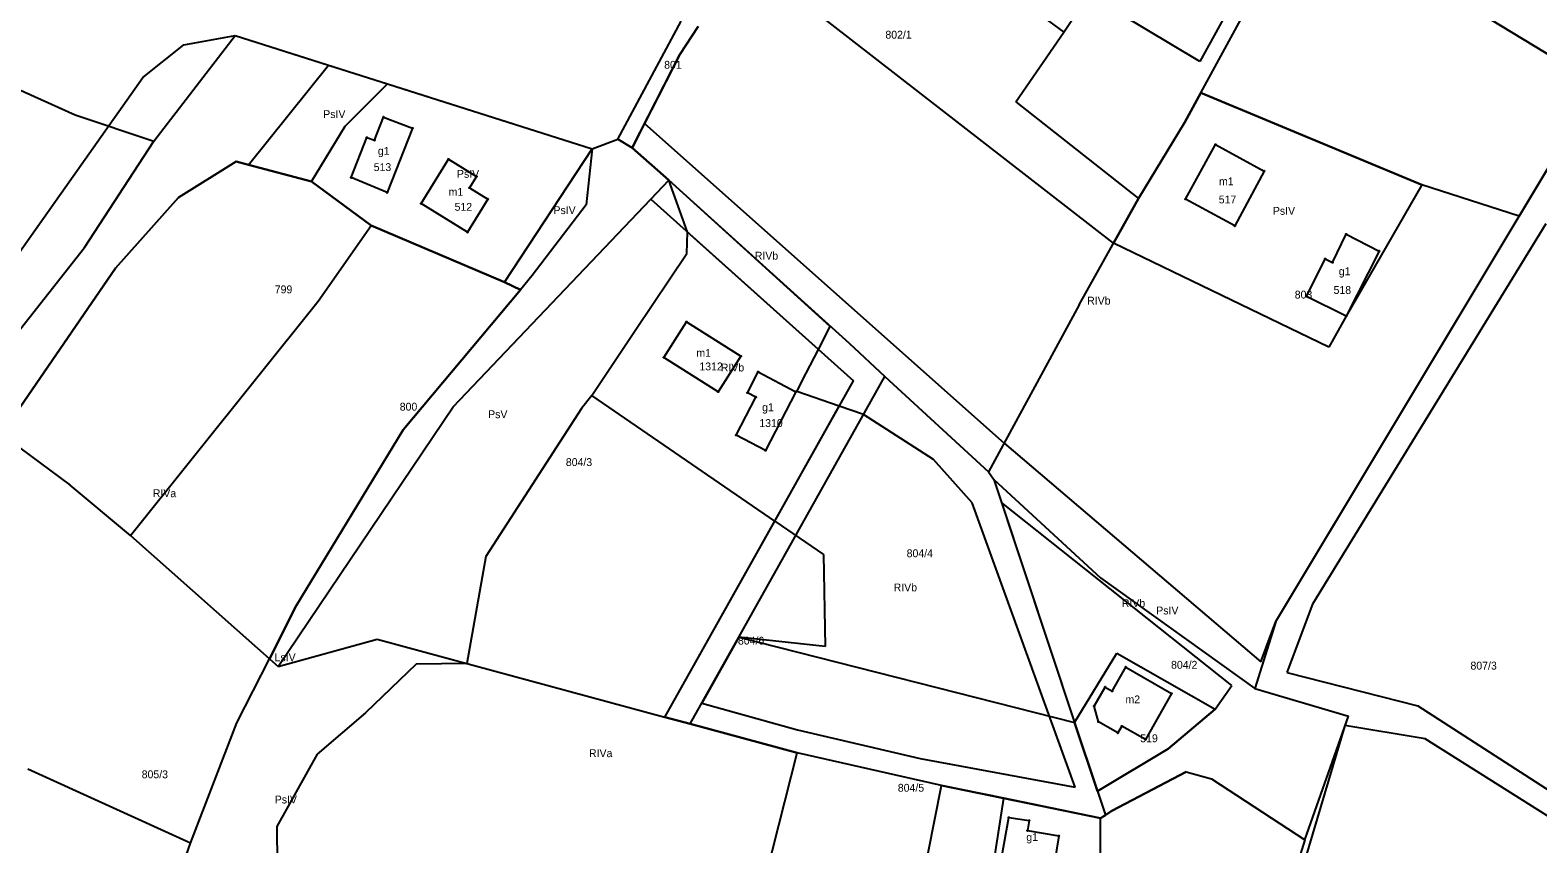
# Model space of a CAD drawing. Extents: x 7498273 to 7499989, y 5499795 to 5500810.
# Drawn here: x 7499540.8 to 7499828.5, y 5500455.2 to 5500610.4 of the extents above; entities that cross this region are included whole.
import ezdxf

# ---------------------------------------------------------------- set-up
doc = ezdxf.new("R2010")
doc.units = 0
for name, color, linetype in [('209-oznaczenie konturu klasyfikacyjnego', 7, 'Continuous'), ('211-numer działki ewidencyjnej', 7, 'Continuous'), ('217-kontur klasyfikacyjny', 7, 'Continuous'), ('218-kontur użytku gruntowego', 7, 'Continuous'), ('219-działka ewidencyjna', 7, 'Continuous'), ('312-budynek ewidencyjny', 7, 'Continuous'), ('312-oznaczenie budynku ewidencyjnego', 7, 'Continuous'), ('312-oznaczenie budynku ewidencyjnego-Atr117', 7, 'Continuous'), ('Punkt budynku', 7, 'Continuous')]:
    doc.layers.add(name, color=color, linetype=linetype)

# ---------------------------------------------------------------- blocks, each defined once
blk = doc.blocks.new('PUNKTBUD')
blk.add_circle((0, 0), 0.09)

msp = doc.modelspace()

# ---------------------------------------------------------------- linework, layer by layer
at = {"layer": '217-kontur klasyfikacyjny'}
for points in [[(7499782.19, 5500637.42), (7499764.06, 5500604.45)], [(7499747.57, 5500569.82), (7499677.4, 5500624.27)], [(7499764.06, 5500604.45), (7499742.82, 5500617.18)], [(7499834.34, 5500603.52), (7499810.94, 5500617.72)], [(7499652.99, 5500589.67), (7499665.04, 5500612.13)], [(7499668.27, 5500611.12), (7499664.76, 5500605.77)], [(7499570.16, 5500607.65), (7499579.96, 5500609.42)], [(7499579.96, 5500609.42), (7499597.74, 5500603.77)], [(7499562.3, 5500601.38), (7499570.16, 5500607.65)], [(7499664.76, 5500605.77), (7499658.06, 5500592.6)], [(7499582.5, 5500584.75), (7499597.74, 5500603.77)], [(7499597.74, 5500603.77), (7499608.98, 5500600.19)], [(7499510.25, 5500527.83), (7499562.3, 5500601.38)], [(7499600.91, 5500592.12), (7499608.98, 5500600.19)], [(7499608.98, 5500600.19), (7499648.04, 5500587.78)], [(7499840.58, 5500600.88), (7499825, 5500574.96)], [(7499764.22, 5500598.47), (7499761.17, 5500592.86)], [(7499806.37, 5500580.96), (7499764.22, 5500598.47)], [(7499594.48, 5500581.56), (7499600.91, 5500592.12)], [(7499658.06, 5500592.6), (7499655.7, 5500587.96)], [(7499658.06, 5500592.6), (7499726.67, 5500531.63)], [(7499761.17, 5500592.86), (7499752.34, 5500578.34)], [(7499648.04, 5500587.78), (7499652.99, 5500589.67)], [(7499655.7, 5500587.96), (7499652.99, 5500589.67)], [(7499662.69, 5500581.79), (7499655.7, 5500587.96)], [(7499569.1, 5500578.53), (7499580.15, 5500585.35)], [(7499580.15, 5500585.35), (7499582.5, 5500584.75)], [(7499631.32, 5500562.36), (7499648.04, 5500587.78)], [(7499648.04, 5500587.78), (7499646.93, 5500577.12)], [(7499582.5, 5500584.75), (7499594.48, 5500581.56)], [(7499594.48, 5500581.56), (7499605.9, 5500573.18)], [(7499659.25, 5500578.17), (7499662.69, 5500581.79)], [(7499666.26, 5500571.89), (7499662.69, 5500581.79)], [(7499693.51, 5500553.92), (7499662.69, 5500581.79)], [(7499806.37, 5500580.96), (7499791.93, 5500555.85)], [(7499825, 5500574.96), (7499806.37, 5500580.96)], [(7499557.08, 5500565.02), (7499569.1, 5500578.53)], [(7499621.53, 5500538.55), (7499659.25, 5500578.17)], [(7499646.93, 5500577.12), (7499636.62, 5500563.62)], [(7499752.34, 5500578.34), (7499747.57, 5500569.82)], [(7499778.52, 5500497.64), (7499825, 5500574.96)], [(7499830.07, 5500573.47), (7499785.55, 5500500.92)], [(7499605.9, 5500573.18), (7499631.32, 5500562.36)], [(7499666.1, 5500567.8), (7499666.26, 5500571.89)], [(7499691.23, 5500549.52), (7499666.26, 5500571.89)], [(7499656.38, 5500553.32), (7499666.1, 5500567.8)], [(7499788.66, 5500549.97), (7499747.57, 5500569.82)], [(7499535.15, 5500533.06), (7499557.08, 5500565.02)], [(7499631.32, 5500562.36), (7499634.36, 5500560.92)], [(7499636.62, 5500563.62), (7499634.36, 5500560.92)], [(7499634.36, 5500560.92), (7499611.98, 5500534.17)], [(7499647.98, 5500540.77), (7499656.38, 5500553.32)], [(7499691.23, 5500549.52), (7499693.51, 5500553.92)], [(7499791.93, 5500555.85), (7499788.66, 5500549.97)], [(7499688.9, 5500545.02), (7499691.23, 5500549.52)], [(7499687.09, 5500541.53), (7499688.9, 5500545.02)], [(7499647.98, 5500540.77), (7499646.03, 5500538.24)], [(7499682.89, 5500516.77), (7499647.98, 5500540.77)], [(7499695.23, 5500538.74), (7499687.09, 5500541.53)], [(7499588.15, 5500489.04), (7499621.53, 5500538.55)], [(7499646.03, 5500538.24), (7499627.75, 5500510.02)], [(7499682.89, 5500516.77), (7499695.23, 5500538.74)], [(7499699.86, 5500537.15), (7499695.23, 5500538.74)], [(7499713.23, 5500528.52), (7499699.86, 5500537.15)], [(7499611.98, 5500534.17), (7499591.6, 5500500.63)], [(7499726.67, 5500531.63), (7499775.7, 5500489.91)], [(7499720.61, 5500520.24), (7499713.23, 5500528.52)], [(7499740.24, 5500466.02), (7499720.61, 5500520.24)], [(7499726.16, 5500520.36), (7499740.11, 5500478.38)], [(7499770.11, 5500485.44), (7499726.16, 5500520.36)], [(7499661.91, 5500479.41), (7499682.89, 5500516.77)], [(7499682.89, 5500516.77), (7499692.22, 5500510.41)], [(7499692.22, 5500510.41), (7499692.5, 5500492.87)], [(7499627.75, 5500510.02), (7499624.17, 5500489.62)], [(7499591.6, 5500500.63), (7499586.46, 5500490.54)], [(7499785.55, 5500500.92), (7499780.66, 5500487.93)], [(7499775.7, 5500489.91), (7499778.52, 5500497.64)], [(7499588.15, 5500489.04), (7499607.04, 5500494.25)], [(7499607.04, 5500494.25), (7499624.17, 5500489.62)], [(7499676.04, 5500494.67), (7499668.96, 5500482.06)], [(7499692.5, 5500492.87), (7499676.04, 5500494.67)], [(7499580.22, 5500478.28), (7499586.46, 5500490.54)], [(7499586.46, 5500490.54), (7499588.15, 5500489.04)], [(7499740.11, 5500478.38), (7499748.19, 5500491.62)], [(7499748.19, 5500491.62), (7499766.95, 5500480.9)], [(7499614.45, 5500489.5), (7499604.79, 5500480.23)], [(7499624.17, 5500489.62), (7499614.45, 5500489.5)], [(7499780.66, 5500487.93), (7499805.62, 5500481.56)], [(7499766.95, 5500480.9), (7499770.11, 5500485.44)], [(7499668.96, 5500482.06), (7499687.27, 5500476.99)], [(7499805.62, 5500481.56), (7499844.69, 5500456.35)], [(7499604.79, 5500480.23), (7499595.61, 5500472.31)], [(7499666.74, 5500478.1), (7499661.91, 5500479.41)], [(7499766.95, 5500480.9), (7499757.96, 5500473.34)], [(7499571.38, 5500455.35), (7499580.22, 5500478.28)], [(7499687.21, 5500472.56), (7499666.74, 5500478.1)], [(7499687.27, 5500476.99), (7499710.65, 5500471.47)], [(7499744.5, 5500465.27), (7499740.11, 5500478.38)], [(7499791.73, 5500477.78), (7499776.34, 5500426.27)], [(7499807.05, 5500475.27), (7499791.73, 5500477.78)], [(7499757.96, 5500473.34), (7499744.5, 5500465.27)], [(7499845.38, 5500451.07), (7499807.05, 5500475.27)], [(7499595.61, 5500472.31), (7499587.88, 5500458.53)], [(7499714.75, 5500466.36), (7499687.21, 5500472.56)], [(7499710.65, 5500471.47), (7499740.24, 5500466.02)], [(7499571.38, 5500455.35), (7499540.34, 5500469.47)], [(7499747.23, 5500461.51), (7499761.43, 5500468.97)], [(7499761.43, 5500468.97), (7499766.26, 5500467.6)], [(7499766.26, 5500467.6), (7499784.04, 5500455.98)], [(7499726.6, 5500463.92), (7499714.75, 5500466.36)], [(7499722.55, 5500437.72), (7499726.6, 5500463.92)], [(7499745.1, 5500460.12), (7499726.6, 5500463.92)], [(7499745.1, 5500460.12), (7499747.23, 5500461.51)], [(7499587.88, 5500458.53), (7499588.02, 5500444.18)], [(7499745.06, 5500447.6), (7499745.1, 5500460.12)], [(7499784.04, 5500455.98), (7499779.48, 5500441.28)], [(7499566.88, 5500442.52), (7499571.38, 5500455.35)]]:
    msp.add_lwpolyline(points, dxfattribs=at)
at = {"layer": '218-kontur użytku gruntowego'}
for points in [[(7499782.19, 5500637.42), (7499764.06, 5500604.45)], [(7499747.57, 5500569.82), (7499677.4, 5500624.27)], [(7499764.06, 5500604.45), (7499742.82, 5500617.18)], [(7499834.34, 5500603.52), (7499810.94, 5500617.72)], [(7499652.99, 5500589.67), (7499665.04, 5500612.13)], [(7499668.27, 5500611.12), (7499664.76, 5500605.77)], [(7499570.16, 5500607.65), (7499579.96, 5500609.42)], [(7499579.96, 5500609.42), (7499597.74, 5500603.77)], [(7499562.3, 5500601.38), (7499570.16, 5500607.65)], [(7499664.76, 5500605.77), (7499658.06, 5500592.6)], [(7499582.5, 5500584.75), (7499597.74, 5500603.77)], [(7499597.74, 5500603.77), (7499608.98, 5500600.19)], [(7499510.25, 5500527.83), (7499562.3, 5500601.38)], [(7499600.91, 5500592.12), (7499608.98, 5500600.19)], [(7499608.98, 5500600.19), (7499648.04, 5500587.78)], [(7499825, 5500574.96), (7499840.58, 5500600.88)], [(7499761.17, 5500592.86), (7499764.22, 5500598.47)], [(7499764.22, 5500598.47), (7499806.37, 5500580.96)], [(7499594.48, 5500581.56), (7499600.91, 5500592.12)], [(7499658.06, 5500592.6), (7499655.7, 5500587.96)], [(7499658.06, 5500592.6), (7499726.67, 5500531.63)], [(7499752.34, 5500578.34), (7499761.17, 5500592.86)], [(7499648.04, 5500587.78), (7499652.99, 5500589.67)], [(7499655.7, 5500587.96), (7499652.99, 5500589.67)], [(7499662.69, 5500581.79), (7499655.7, 5500587.96)], [(7499580.15, 5500585.35), (7499569.1, 5500578.53)], [(7499582.5, 5500584.75), (7499580.15, 5500585.35)], [(7499631.32, 5500562.36), (7499648.04, 5500587.78)], [(7499648.04, 5500587.78), (7499646.93, 5500577.12)], [(7499594.48, 5500581.56), (7499582.5, 5500584.75)], [(7499605.9, 5500573.18), (7499594.48, 5500581.56)], [(7499659.25, 5500578.17), (7499662.69, 5500581.79)], [(7499666.26, 5500571.89), (7499662.69, 5500581.79)], [(7499693.51, 5500553.92), (7499662.69, 5500581.79)], [(7499806.37, 5500580.96), (7499791.93, 5500555.85)], [(7499825, 5500574.96), (7499806.37, 5500580.96)], [(7499569.1, 5500578.53), (7499557.08, 5500565.02)], [(7499621.53, 5500538.55), (7499659.25, 5500578.17)], [(7499646.93, 5500577.12), (7499636.62, 5500563.62)], [(7499747.57, 5500569.82), (7499752.34, 5500578.34)], [(7499778.52, 5500497.64), (7499825, 5500574.96)], [(7499830.07, 5500573.47), (7499785.55, 5500500.92)], [(7499631.32, 5500562.36), (7499605.9, 5500573.18)], [(7499666.1, 5500567.8), (7499666.26, 5500571.89)], [(7499691.23, 5500549.52), (7499666.26, 5500571.89)], [(7499656.38, 5500553.32), (7499666.1, 5500567.8)], [(7499788.66, 5500549.97), (7499747.57, 5500569.82)], [(7499557.08, 5500565.02), (7499535.15, 5500533.06)], [(7499634.36, 5500560.92), (7499631.32, 5500562.36)], [(7499636.62, 5500563.62), (7499634.36, 5500560.92)], [(7499611.98, 5500534.17), (7499634.36, 5500560.92)], [(7499647.98, 5500540.77), (7499656.38, 5500553.32)], [(7499691.23, 5500549.52), (7499693.51, 5500553.92)], [(7499791.93, 5500555.85), (7499788.66, 5500549.97)], [(7499688.9, 5500545.02), (7499691.23, 5500549.52)], [(7499687.09, 5500541.53), (7499688.9, 5500545.02)], [(7499647.98, 5500540.77), (7499646.03, 5500538.24)], [(7499682.89, 5500516.77), (7499647.98, 5500540.77)], [(7499695.23, 5500538.74), (7499687.09, 5500541.53)], [(7499588.15, 5500489.04), (7499621.53, 5500538.55)], [(7499646.03, 5500538.24), (7499627.75, 5500510.02)], [(7499682.89, 5500516.77), (7499695.23, 5500538.74)], [(7499699.86, 5500537.15), (7499695.23, 5500538.74)], [(7499713.23, 5500528.52), (7499699.86, 5500537.15)], [(7499591.6, 5500500.63), (7499611.98, 5500534.17)], [(7499726.67, 5500531.63), (7499775.7, 5500489.91)], [(7499720.61, 5500520.24), (7499713.23, 5500528.52)], [(7499740.24, 5500466.02), (7499720.61, 5500520.24)], [(7499726.16, 5500520.36), (7499740.11, 5500478.38)], [(7499770.11, 5500485.44), (7499726.16, 5500520.36)], [(7499661.91, 5500479.41), (7499682.89, 5500516.77)], [(7499682.89, 5500516.77), (7499692.22, 5500510.41)], [(7499692.22, 5500510.41), (7499692.5, 5500492.87)], [(7499627.75, 5500510.02), (7499624.17, 5500489.62)], [(7499586.46, 5500490.54), (7499591.6, 5500500.63)], [(7499785.55, 5500500.92), (7499780.66, 5500487.93)], [(7499775.7, 5500489.91), (7499778.52, 5500497.64)], [(7499588.15, 5500489.04), (7499607.04, 5500494.25)], [(7499607.04, 5500494.25), (7499624.17, 5500489.62)], [(7499676.04, 5500494.67), (7499668.96, 5500482.06)], [(7499692.5, 5500492.87), (7499676.04, 5500494.67)], [(7499580.22, 5500478.28), (7499586.46, 5500490.54)], [(7499586.46, 5500490.54), (7499588.15, 5500489.04)], [(7499740.11, 5500478.38), (7499748.19, 5500491.62)], [(7499748.19, 5500491.62), (7499766.95, 5500480.9)], [(7499614.45, 5500489.5), (7499604.79, 5500480.23)], [(7499624.17, 5500489.62), (7499614.45, 5500489.5)], [(7499780.66, 5500487.93), (7499805.62, 5500481.56)], [(7499766.95, 5500480.9), (7499770.11, 5500485.44)], [(7499668.96, 5500482.06), (7499687.27, 5500476.99)], [(7499805.62, 5500481.56), (7499844.69, 5500456.35)], [(7499604.79, 5500480.23), (7499595.61, 5500472.31)], [(7499666.74, 5500478.1), (7499661.91, 5500479.41)], [(7499757.96, 5500473.34), (7499766.95, 5500480.9)], [(7499571.38, 5500455.35), (7499580.22, 5500478.28)], [(7499687.21, 5500472.56), (7499666.74, 5500478.1)], [(7499687.27, 5500476.99), (7499710.65, 5500471.47)], [(7499740.11, 5500478.38), (7499744.5, 5500465.27)], [(7499791.73, 5500477.78), (7499776.34, 5500426.27)], [(7499807.05, 5500475.27), (7499791.73, 5500477.78)], [(7499744.5, 5500465.27), (7499757.96, 5500473.34)], [(7499845.38, 5500451.07), (7499807.05, 5500475.27)], [(7499595.61, 5500472.31), (7499587.88, 5500458.53)], [(7499714.75, 5500466.36), (7499687.21, 5500472.56)], [(7499710.65, 5500471.47), (7499740.24, 5500466.02)], [(7499571.38, 5500455.35), (7499540.34, 5500469.47)], [(7499747.23, 5500461.51), (7499761.43, 5500468.97)], [(7499761.43, 5500468.97), (7499766.26, 5500467.6)], [(7499766.26, 5500467.6), (7499784.04, 5500455.98)], [(7499726.6, 5500463.92), (7499714.75, 5500466.36)], [(7499722.55, 5500437.72), (7499726.6, 5500463.92)], [(7499745.1, 5500460.12), (7499726.6, 5500463.92)], [(7499745.1, 5500460.12), (7499747.23, 5500461.51)], [(7499587.88, 5500458.53), (7499588.02, 5500444.18)], [(7499745.06, 5500447.6), (7499745.1, 5500460.12)], [(7499784.04, 5500455.98), (7499779.48, 5500441.28)], [(7499566.88, 5500442.52), (7499571.38, 5500455.35)]]:
    msp.add_lwpolyline(points, dxfattribs=at)
at = {"layer": '219-działka ewidencyjna'}
for points in [[(7499738.09, 5500610.06), (7499764.64, 5500650.03)], [(7499761.17, 5500592.86), (7499784.51, 5500635.75)], [(7499720.67, 5500622.88), (7499738.09, 5500610.06)], [(7499810.94, 5500617.72), (7499834.34, 5500603.52)], [(7499652.99, 5500589.67), (7499665.04, 5500612.13)], [(7499664.76, 5500605.77), (7499668.27, 5500611.12)], [(7499514.94, 5500609.79), (7499549.39, 5500594.26)], [(7499564.43, 5500589.27), (7499579.96, 5500609.42)], [(7499579.96, 5500609.42), (7499648.04, 5500587.78)], [(7499728.91, 5500596.76), (7499738.09, 5500610.06)], [(7499655.7, 5500587.96), (7499664.76, 5500605.77)], [(7499778.52, 5500497.64), (7499840.58, 5500600.88)], [(7499728.91, 5500596.76), (7499752.34, 5500578.34)], [(7499549.39, 5500594.26), (7499564.43, 5500589.27)], [(7499752.34, 5500578.34), (7499761.17, 5500592.86)], [(7499551.17, 5500568.97), (7499564.43, 5500589.27)], [(7499648.04, 5500587.78), (7499652.99, 5500589.67)], [(7499652.99, 5500589.67), (7499655.7, 5500587.96)], [(7499655.7, 5500587.96), (7499662.69, 5500581.79)], [(7499631.32, 5500562.36), (7499648.04, 5500587.78)], [(7499659.25, 5500578.17), (7499662.69, 5500581.79)], [(7499662.69, 5500581.79), (7499697.08, 5500550.7)], [(7499621.53, 5500538.55), (7499659.25, 5500578.17)], [(7499659.25, 5500578.17), (7499697.92, 5500543.53)], [(7499740.98, 5500558.04), (7499752.34, 5500578.34)], [(7499595.78, 5500558.73), (7499605.9, 5500573.18)], [(7499605.9, 5500573.18), (7499631.32, 5500562.36)], [(7499526.94, 5500538.25), (7499551.17, 5500568.97)], [(7499559.98, 5500514.06), (7499595.78, 5500558.73)], [(7499740.98, 5500558.04), (7499723.7, 5500526.16)], [(7499697.08, 5500550.7), (7499703.92, 5500544.39)], [(7499661.91, 5500479.41), (7499697.92, 5500543.53)], [(7499676.04, 5500494.67), (7499703.92, 5500544.39)], [(7499703.92, 5500544.39), (7499723.7, 5500526.16)], [(7499588.15, 5500489.04), (7499621.53, 5500538.55)], [(7499538.81, 5500530.74), (7499548.42, 5500523.66)], [(7499723.7, 5500526.16), (7499724.73, 5500524.73)], [(7499724.73, 5500524.73), (7499740.11, 5500478.38)], [(7499724.73, 5500524.73), (7499745.04, 5500505.97)], [(7499559.98, 5500514.06), (7499548.42, 5500523.66)], [(7499559.98, 5500514.06), (7499588.15, 5500489.04)], [(7499745.04, 5500505.97), (7499774.52, 5500484.82)], [(7499778.52, 5500497.64), (7499774.52, 5500484.82)], [(7499588.15, 5500489.04), (7499607.04, 5500494.25)], [(7499607.04, 5500494.25), (7499661.91, 5500479.41)], [(7499666.74, 5500478.1), (7499676.04, 5500494.67)], [(7499676.04, 5500494.67), (7499740.11, 5500478.38)], [(7499774.52, 5500484.82), (7499792.43, 5500479.56)], [(7499661.91, 5500479.41), (7499666.74, 5500478.1)], [(7499784.04, 5500455.98), (7499792.43, 5500479.56)], [(7499666.74, 5500478.1), (7499687.21, 5500472.56)], [(7499740.11, 5500478.38), (7499746.04, 5500460.68)], [(7499678.99, 5500440.23), (7499687.21, 5500472.56)], [(7499761.43, 5500468.97), (7499747.23, 5500461.51)], [(7499761.43, 5500468.97), (7499766.26, 5500467.6)], [(7499766.26, 5500467.6), (7499784.04, 5500455.98)], [(7499712.18, 5500453.53), (7499714.75, 5500466.36)], [(7499714.75, 5500466.36), (7499745.1, 5500460.12)], [(7499746.04, 5500460.68), (7499747.23, 5500461.51)], [(7499745.1, 5500460.12), (7499746.04, 5500460.68)], [(7499784.04, 5500455.98), (7499779.48, 5500441.28)]]:
    msp.add_lwpolyline(points, dxfattribs=at)
at = {"layer": '312-budynek ewidencyjny'}
for points in [[(7499606.51, 5500589.44), (7499608.23, 5500593.86)], [(7499608.23, 5500593.86), (7499613.77, 5500591.71)], [(7499613.77, 5500591.71), (7499608.96, 5500579.46)], [(7499602.08, 5500582.31), (7499605.03, 5500589.95)], [(7499605.03, 5500589.95), (7499606.51, 5500589.44)], [(7499761.31, 5500578.22), (7499767.02, 5500588.6)], [(7499767.02, 5500588.6), (7499776.33, 5500583.55)], [(7499615.42, 5500577.36), (7499620.63, 5500585.8)], [(7499620.63, 5500585.8), (7499625.96, 5500582.51)], [(7499608.96, 5500579.46), (7499602.08, 5500582.31)], [(7499625.96, 5500582.51), (7499624.64, 5500580.38)], [(7499776.33, 5500583.55), (7499770.69, 5500573.09)], [(7499624.64, 5500580.38), (7499628.16, 5500578.21)], [(7499624.29, 5500571.87), (7499615.42, 5500577.36)], [(7499628.16, 5500578.21), (7499624.29, 5500571.87)], [(7499770.69, 5500573.09), (7499761.31, 5500578.22)], [(7499789.32, 5500566.13), (7499791.98, 5500571.52)], [(7499791.98, 5500571.52), (7499798.26, 5500568.29)], [(7499798.26, 5500568.29), (7499791.93, 5500555.85)], [(7499784.38, 5500559.63), (7499787.93, 5500566.81)], [(7499787.93, 5500566.81), (7499789.32, 5500566.13)], [(7499791.93, 5500555.85), (7499784.38, 5500559.63)], [(7499661.75, 5500548), (7499666.05, 5500554.78)], [(7499666.05, 5500554.78), (7499676.41, 5500548.24)], [(7499672.12, 5500541.45), (7499661.75, 5500548)], [(7499676.41, 5500548.24), (7499672.12, 5500541.45)], [(7499677.68, 5500541.26), (7499679.72, 5500545.23)], [(7499679.72, 5500545.23), (7499686.96, 5500541.45)], [(7499675.56, 5500533.19), (7499679.28, 5500540.44)], [(7499679.28, 5500540.44), (7499677.68, 5500541.26)], [(7499686.96, 5500541.45), (7499681.13, 5500530.25)], [(7499681.13, 5500530.25), (7499675.56, 5500533.19)], [(7499747.29, 5500484.37), (7499749.92, 5500488.93)], [(7499749.92, 5500488.93), (7499758.65, 5500483.9)], [(7499743.85, 5500481.51), (7499745.96, 5500485.13)], [(7499745.96, 5500485.13), (7499747.29, 5500484.37)], [(7499744.69, 5500478.52), (7499743.85, 5500481.51)], [(7499758.65, 5500483.9), (7499753.67, 5500475.1)], [(7499748.39, 5500476.38), (7499744.69, 5500478.52)], [(7499749.12, 5500477.67), (7499748.39, 5500476.38)], [(7499753.67, 5500475.1), (7499749.12, 5500477.67)], [(7499726.24, 5500452.83), (7499727.58, 5500460.22)], [(7499727.58, 5500460.22), (7499731.49, 5500459.65)], [(7499731.49, 5500459.65), (7499731.17, 5500457.74)], [(7499731.17, 5500457.74), (7499737.14, 5500456.74)], [(7499737.14, 5500456.74), (7499736.23, 5500451.3)]]:
    msp.add_lwpolyline(points, dxfattribs=at)

# ---------------------------------------------------------------- block references
at = {"layer": 'Punkt budynku'}
for p in [(7499608.23, 5500593.86), (7499613.77, 5500591.71), (7499605.03, 5500589.95), (7499606.51, 5500589.44), (7499767.02, 5500588.6), (7499620.63, 5500585.8), (7499602.08, 5500582.31), (7499625.96, 5500582.51), (7499776.33, 5500583.55), (7499608.96, 5500579.46), (7499624.64, 5500580.38), (7499615.42, 5500577.36), (7499628.16, 5500578.21), (7499761.31, 5500578.22), (7499624.29, 5500571.87), (7499770.69, 5500573.09), (7499791.98, 5500571.52), (7499798.26, 5500568.29), (7499787.93, 5500566.81), (7499789.32, 5500566.13), (7499784.38, 5500559.63), (7499666.05, 5500554.78), (7499791.93, 5500555.85), (7499661.75, 5500548), (7499676.41, 5500548.24), (7499679.72, 5500545.23), (7499672.12, 5500541.45), (7499677.68, 5500541.26), (7499679.28, 5500540.44), (7499686.96, 5500541.45), (7499675.56, 5500533.19), (7499681.13, 5500530.25), (7499749.92, 5500488.93), (7499745.96, 5500485.13), (7499747.29, 5500484.37), (7499743.85, 5500481.51), (7499758.65, 5500483.9), (7499744.69, 5500478.52), (7499748.39, 5500476.38), (7499749.12, 5500477.67), (7499753.67, 5500475.1), (7499727.58, 5500460.22), (7499731.49, 5500459.65), (7499731.17, 5500457.74), (7499737.14, 5500456.74)]:
    msp.add_blockref('PUNKTBUD', p, dxfattribs=at)

# ---------------------------------------------------------------- texts
at = {"layer": '209-oznaczenie konturu klasyfikacyjnego'}
for s, p in [('PsIV', (7499596.74, 5500593.67)), ('PsIV', (7499622.26, 5500582.28)), ('PsIV', (7499640.68, 5500575.35)), ('PsIV', (7499777.97, 5500575.22)), ('RIVb', (7499679.1, 5500566.66)), ('RIVb', (7499742.53, 5500558.09)), ('RIVb', (7499672.61, 5500545.33)), ('PsV', (7499628.21, 5500536.42)), ('RIVa', (7499564.22, 5500521.35)), ('RIVb', (7499705.6, 5500503.38)), ('RIVb', (7499749.14, 5500500.37)), ('PsIV', (7499755.71, 5500498.98)), ('LsIV', (7499587.46, 5500490.04)), ('RIVa', (7499647.46, 5500471.76)), ('PsIV', (7499587.49, 5500462.92))]:
    msp.add_text(s, height=1.5, dxfattribs=at).set_placement(p)
at = {"layer": '211-numer działki ewidencyjnej'}
for s, p in [('802/1', (7499704.02, 5500608.82)), ('801', (7499661.8, 5500603.08)), ('799', (7499587.49, 5500560.24)), ('803', (7499782.14, 5500559.24)), ('800', (7499611.34, 5500537.86)), ('804/3', (7499643.04, 5500527.29)), ('804/4', (7499708.08, 5500509.89)), ('804/6', (7499675.88, 5500493.23)), ('804/2', (7499758.54, 5500488.62)), ('807/3', (7499815.68, 5500488.46)), ('805/3', (7499562.09, 5500467.73)), ('804/5', (7499706.39, 5500465.16))]:
    msp.add_text(s, height=1.5, dxfattribs=at).set_placement(p)
at = {"layer": '312-oznaczenie budynku ewidencyjnego'}
for s, p in [('513', (7499606.37, 5500583.56)), ('512', (7499621.8, 5500575.98)), ('517', (7499767.64, 5500577.39)), ('518', (7499789.55, 5500560.12)), ('1312', (7499668.52, 5500545.54)), ('1310', (7499679.96, 5500534.73)), ('519', (7499752.66, 5500474.6))]:
    msp.add_text(s, height=1.5, dxfattribs=at).set_placement(p)
at = {"layer": '312-oznaczenie budynku ewidencyjnego-Atr117'}
for s, p in [('g1', (7499607.159, 5500586.66)), ('m1', (7499767.695, 5500580.85)), ('m1', (7499620.665, 5500578.84)), ('g1', (7499790.549, 5500563.69)), ('m1', (7499667.955, 5500548.12)), ('g1', (7499680.489, 5500537.74)), ('m2', (7499749.836, 5500482.02)), ('g1', (7499730.919, 5500455.76))]:
    msp.add_text(s, height=1.5, dxfattribs=at).set_placement(p)

doc.saveas('drawing.dxf')
